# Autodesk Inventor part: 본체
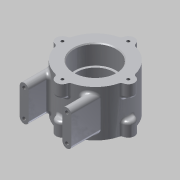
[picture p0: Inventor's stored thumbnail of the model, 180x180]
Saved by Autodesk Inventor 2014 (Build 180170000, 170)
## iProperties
Created: 2015-03
Part Number: 본체
Material: 알루미늄 6061
Document SubType Name: Modeling
Designer: MYHOME
Mass: 450.776 g
Surface Area: 332.745 cm^2
Volume: 166.338 cm^3
Density: 2.71 g/cm^3
Appearance: 알루미늄 - 평지
Author: MYHOME
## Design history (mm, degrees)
sketch "스케치1"
  geometry: C1 r 37 at (0, 0); 1 further point
  constraints: 1 centre point, 1 coincident
  dimensions: "d0" = 74 diameter of C1
extrude "돌출1" new body sketch "스케치1" stored distance "d1" = 52; taper "d2" = 0 deg
sketch "스케치2"
  geometry: C1 r 7 at (0, 37); C2 r 7 at (-37, 0); C3 r 7 at (0, -37); C4 r 7 at (37, 0); A1 r 37 centre (0, 0) between (0, 37) and (-37, 0) reference
  constraints: 4 centre point, 4 point on circle, 3 equal radius, 2 horizontal alignment, 2 vertical alignment
  dimensions: "d3" = 7 radius of C2
extrude "돌출2" join sketch "스케치2" distance "d4" = 15; taper "d5" = 0 deg
sketch "스케치3"
  geometry: A1 r 7 centre (0, 37) between (6.969, 36.338) and (-6.969, 36.338) reference; A2 r 7 centre (-37, 0) between (-36.338, 6.969) and (-36.338, -6.969) reference; A3 r 7 centre (0, -37) between (-6.969, -36.338) and (6.969, -36.338) reference; A4 r 7 centre (37, 0) between (36.338, -6.969) and (36.338, 6.969) reference; 4 further points
  constraints: 4 coincident
hole "구멍1" sketch "스케치3" at (-37, 0), (0, 37), (0, -37), (37, 0) diameter "d6" = 3.242; stored, may be unused: countersink angle "d10" = 90 deg, drill point angle "d12" = 118 deg; dims "d7" = 8, "d8" = 4, "d9" = 2, "d11" = 11
sketch "스케치4"
  geometry: L1 (-29, -56)-(-19, -56); L2 (-19, -56)-(-19, -31.749); L3 (-29, -22.978)-(-29, -56); C1 r 1.621 at (0, -37) reference; C2 r 1.621 at (-37, 0) reference; C3 r 1.621 at (0, 37) reference; C4 r 1.621 at (37, 0) reference; A1 r 37 centre (0, 0) between (6.969, -36.338) and (36.338, -6.969) reference; A2 r 7 centre (0, -37) between (-6.969, -36.338) and (6.969, -36.338) reference; A3 r 37 centre (0, 0) between (-36.338, -6.969) and (-6.969, -36.338) reference; A4 r 7 centre (-37, 0) between (-36.338, 6.969) and (-36.338, -6.969) reference; A5 r 37 centre (0, 0) between (-6.969, 36.338) and (-36.338, 6.969) reference; A6 r 7 centre (0, 37) between (6.969, 36.338) and (-6.969, 36.338) reference; A7 r 37 centre (0, 0) between (36.338, 6.969) and (6.969, 36.338) reference; A8 r 7 centre (37, 0) between (36.338, -6.969) and (36.338, 6.969) reference; 1 further point
  constraints: 6 end point, 2 point on circle, 1 horizontal, 1 parallel, 1 vertical
  dimensions: "d13" = 10 distance of L1.start L1.end; "d14" = 56 distance from line of L1 point (0, 0); "d15" = 19 distance from line of point (0, 0) L2
extrude "돌출3" join sketch "스케치4" stored distance "d16" = 40; taper "d17" = 0 deg
fillet "모깎기1" dims "d18" = 5
sketch "스케치5"
  geometry: A1 r 5 centre (0, 0) between (-5, 0) and (5, 0) reference; A2 r 5 centre (0, 30) between (5, 30) and (-5, 30) reference; 3 further points
  constraints: 2 coincident
hole "구멍2" sketch "스케치5" at (0, 30), (0, 0) diameter "d19" = 4.134; stored, may be unused: countersink angle "d23" = 90 deg, drill point angle "d25" = 118 deg; dims "d20" = 6, "d21" = 4, "d22" = 2, "d24" = 8
hole "구멍3" diameter "d28" = 47; stored, may be unused: countersink angle "d32" = 90 deg, drill point angle "d34" = 0 deg; dims "d26" = 10, "d27" = 10, "d29" = 6, "d30" = 4, "d31" = 2, "d33" = 22
hole "구멍4" diameter "d37" = 42; stored, may be unused: countersink angle "d41" = 90 deg, drill point angle "d43" = 0 deg; dims "d35" = 10, "d36" = 10, "d38" = 6, "d39" = 4, "d40" = 2, "d42" = 22
fillet "모깎기2" dims "d44" = 0.3
chamfer "모따기1" distance "d45" = 1; stored, may be unused: second distance "d46" = 2, angle "d47" = 45 deg
fillet "모깎기3" dims "d48" = 3
fillet "모깎기4" dims "d49" = 3
fillet "모깎기5" dims "d50" = 3
sketch "스케치6"
  geometry: L1 (0, 0)-(-26.163, 26.163); L2 (0, 0)-(-31.753, 0); C1 r 1.621 at (37, 0) reference; C2 r 1.621 at (0, 37) reference; C3 r 1.621 at (-37, 0) reference; C4 r 1.621 at (0, -37) reference; C5 r 24.5 at (0, 0) reference; A1 r 37 centre (0, 0) between (35.863, 9.104) and (9.104, 35.863) reference; A2 r 3 centre (9.842, 38.77) between (6.889, 38.239) and (9.104, 35.863) reference; A3 r 7 centre (0, 37) between (6.889, 38.239) and (-6.889, 38.239) reference; A4 r 3 centre (-9.842, 38.77) between (-9.104, 35.863) and (-6.889, 38.239) reference; A5 r 3 centre (-38.77, 9.842) between (-38.239, 6.889) and (-35.863, 9.104) reference; A6 r 7 centre (-37, 0) between (-38.239, 6.889) and (-38.239, -6.889) reference; A7 r 3 centre (-38.77, -9.842) between (-35.863, -9.104) and (-38.239, -6.889) reference; A8 r 37 centre (0, 0) between (-35.863, -9.104) and (-9.104, -35.863) reference; A9 r 3 centre (-9.842, -38.77) between (-6.889, -38.239) and (-9.104, -35.863) reference; A10 r 7 centre (0, -37) between (-6.889, -38.239) and (6.889, -38.239) reference; A11 r 3 centre (9.842, -38.77) between (9.104, -35.863) and (6.889, -38.239) reference; A12 r 37 centre (0, 0) between (9.104, -35.863) and (35.863, -9.104) reference; A13 r 3 centre (38.77, -9.842) between (38.239, -6.889) and (35.863, -9.104) reference; A14 r 7 centre (37, 0) between (38.239, -6.889) and (38.239, 6.889) reference; A15 r 3 centre (38.77, 9.842) between (35.863, 9.104) and (38.239, 6.889) reference; A16 r 37 centre (0, 0) between (-9.104, 35.863) and (-35.863, 9.104) reference; 1 further point
  constraints: 4 end point, 1 coincident, 1 horizontal, 1 point on circle
  dimensions: "d51" = 45 deg angle of L1 L2
node "작업 평면1"
sketch "스케치7"
  geometry: L1 (-18.921, -52)-(18.921, -52) reference; 2 further points
  constraints: 1 coincident, 1 other
  dimensions: "d52" = 26 distance from line of L1 point (0, -26)
feature "엠보싱1" sketch "스케치7" dims "d53" = 0.5, "d54" = 0
node "솔리드1"
mirror "대칭1"
mirror "대칭2"
mirror "대칭3"
node "투영된 루프1"
